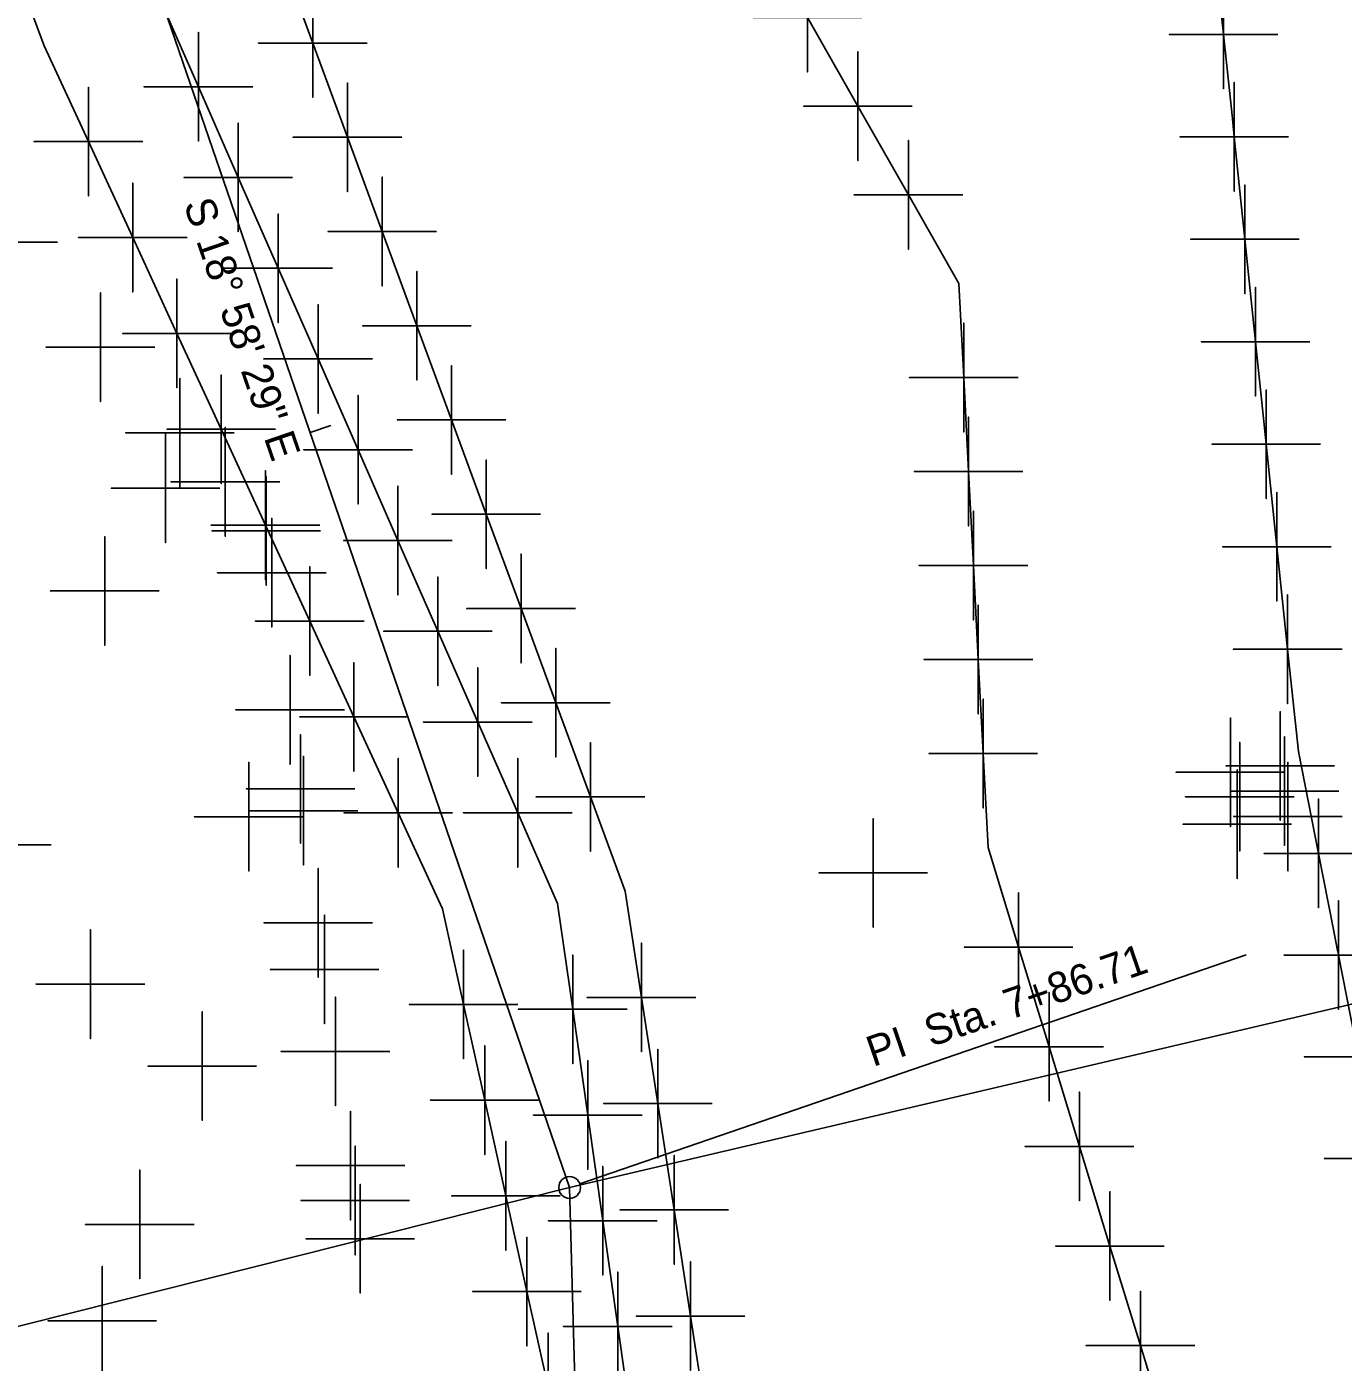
# Model space of a CAD drawing. Extents: x 2260968 to 2264340, y 653057 to 655850.
# Drawn here: x 2261689.1 to 2261749.7, y 654993.6 to 655055 of the extents above; entities that cross this region are included whole.
import ezdxf

# ---------------------------------------------------------------- set-up
doc = ezdxf.new("R2010")
doc.units = 0
for name, color, linetype in [('CL_X_Construction', 7, 'Continuous'), ('Default', 7, 'Continuous'), ('GE_X_CL_10', 7, 'Continuous'), ('GK_Patterns2', 7, 'Continuous')]:
    doc.layers.add(name, color=color, linetype=linetype)

msp = doc.modelspace()

# ---------------------------------------------------------------- linework, layer by layer
at = {"layer": 'CL_X_Construction'}
for p, q in [((2261687.579, 655078.757), (2261714.109, 655001.598)), ((2261687.579, 655078.757), (2261714.109, 655001.598)), ((2261714.109, 655001.598), (2261716.474, 654914.987)), ((2261714.109, 655001.598), (2261716.474, 654914.987))]:
    msp.add_line(p, q, dxfattribs=at)
at = {"layer": 'Default'}
for points in [[(2261720.425, 654990.805), (2261719.672, 654995.689), (2261718.919, 655000.572), (2261718.166, 655005.456), (2261717.413, 655010.339), (2261716.661, 655015.223), (2261715.064, 655019.556), (2261713.468, 655023.89), (2261711.871, 655028.223), (2261710.275, 655032.556), (2261708.678, 655036.889), (2261707.082, 655041.222), (2261705.485, 655045.556), (2261703.889, 655049.889), (2261702.292, 655054.222), (2261700.696, 655058.555), (2261699.362, 655063.307), (2261698.028, 655068.058), (2261696.694, 655072.81), (2261695.36, 655077.561), (2261694.026, 655082.313), (2261692.692, 655087.064), (2261691.423, 655090.297), (2261690.155, 655093.53)], [(2261686.753, 655085.733), (2261687.959, 655081.541), (2261689.164, 655077.349), (2261690.37, 655073.157), (2261691.575, 655068.965), (2261692.781, 655064.773), (2261693.986, 655060.581), (2261695.192, 655056.389), (2261697.028, 655052.215), (2261698.865, 655048.042), (2261700.701, 655043.868), (2261702.538, 655039.695), (2261704.375, 655035.521), (2261706.211, 655031.348), (2261708.048, 655027.174), (2261709.884, 655023.001), (2261711.721, 655018.827), (2261713.557, 655014.654), (2261714.248, 655009.793), (2261714.939, 655004.932), (2261715.63, 655000.071), (2261716.321, 654995.21), (2261717.012, 654990.35)], [(2261713.118, 654992.413), (2261712.146, 654996.814), (2261711.174, 655001.215), (2261710.202, 655005.616), (2261709.231, 655010.017), (2261708.259, 655014.418), (2261706.223, 655018.827), (2261704.188, 655023.236), (2261702.152, 655027.646), (2261700.116, 655032.055), (2261698.081, 655036.464), (2261696.045, 655040.873), (2261694.01, 655045.282), (2261691.974, 655049.691), (2261689.938, 655054.1), (2261688.389, 655058.269)], [(2261725.05, 655055.396), (2261725.05, 655057.896), (2261725.05, 655055.396), (2261722.55, 655055.396), (2261725.05, 655055.396), (2261725.05, 655052.896), (2261725.05, 655055.396), (2261727.55, 655055.396)], [(2261743.887, 655057.515), (2261744.189, 655054.62), (2261744.579, 655050.885), (2261744.595, 655050.73), (2261744.613, 655050.561), (2261744.681, 655049.908), (2261745.173, 655045.197), (2261745.664, 655040.485), (2261746.123, 655036.089), (2261746.156, 655035.774), (2261746.647, 655031.062), (2261747.139, 655026.351), (2261747.63, 655021.639), (2261748.553, 655016.964), (2261749.244, 655013.465), (2261749.435, 655012.496), (2261749.471, 655012.311), (2261749.476, 655012.288), (2261750.399, 655007.613)], [(2261702.292, 655054.222), (2261702.292, 655056.722), (2261702.292, 655054.222), (2261699.792, 655054.222), (2261702.292, 655054.222), (2261702.292, 655051.722), (2261702.292, 655054.222), (2261704.792, 655054.222)], [(2261744.189, 655054.62), (2261744.189, 655057.12), (2261744.189, 655054.62), (2261741.689, 655054.62), (2261744.189, 655054.62), (2261744.189, 655052.12), (2261744.189, 655054.62), (2261746.689, 655054.62)], [(2261741.766, 654989.745), (2261740.364, 654994.327), (2261738.963, 654998.908), (2261737.561, 655003.49), (2261736.16, 655008.071), (2261734.759, 655012.653), (2261733.357, 655017.234), (2261733.133, 655021.556), (2261732.909, 655025.877), (2261732.685, 655030.199), (2261732.461, 655034.521), (2261732.237, 655038.842), (2261732.013, 655043.164), (2261729.692, 655047.241), (2261727.371, 655051.318), (2261725.05, 655055.396)], [(2261697.028, 655052.215), (2261697.028, 655054.715), (2261697.028, 655052.215), (2261694.528, 655052.215), (2261697.028, 655052.215), (2261697.028, 655049.715), (2261697.028, 655052.215), (2261699.528, 655052.215)], [(2261727.371, 655051.318), (2261727.371, 655053.818), (2261727.371, 655051.318), (2261724.871, 655051.318), (2261727.371, 655051.318), (2261727.371, 655048.818), (2261727.371, 655051.318), (2261729.871, 655051.318)], [(2261744.681, 655049.908), (2261744.681, 655052.408), (2261744.681, 655049.908), (2261742.181, 655049.908), (2261744.681, 655049.908), (2261744.681, 655047.408), (2261744.681, 655049.908), (2261747.181, 655049.908)], [(2261691.974, 655049.691), (2261691.974, 655052.191), (2261691.974, 655049.691), (2261689.474, 655049.691), (2261691.974, 655049.691), (2261691.974, 655047.191), (2261691.974, 655049.691), (2261694.474, 655049.691)], [(2261703.889, 655049.889), (2261703.889, 655052.389), (2261703.889, 655049.889), (2261701.389, 655049.889), (2261703.889, 655049.889), (2261703.889, 655047.389), (2261703.889, 655049.889), (2261706.389, 655049.889)], [(2261698.865, 655048.042), (2261698.865, 655050.542), (2261698.865, 655048.042), (2261696.365, 655048.042), (2261698.865, 655048.042), (2261698.865, 655045.542), (2261698.865, 655048.042), (2261701.365, 655048.042)], [(2261729.692, 655047.241), (2261729.692, 655049.741), (2261729.692, 655047.241), (2261727.192, 655047.241), (2261729.692, 655047.241), (2261729.692, 655044.741), (2261729.692, 655047.241), (2261732.192, 655047.241)], [(2261688.044, 655045.071), (2261688.044, 655047.571), (2261688.044, 655045.071), (2261685.544, 655045.071), (2261688.044, 655045.071), (2261688.044, 655042.571), (2261688.044, 655045.071), (2261690.544, 655045.071)], [(2261694.01, 655045.282), (2261694.01, 655047.782), (2261694.01, 655045.282), (2261691.51, 655045.282), (2261694.01, 655045.282), (2261694.01, 655042.782), (2261694.01, 655045.282), (2261696.51, 655045.282)], [(2261705.485, 655045.556), (2261705.485, 655048.056), (2261705.485, 655045.556), (2261702.985, 655045.556), (2261705.485, 655045.556), (2261705.485, 655043.056), (2261705.485, 655045.556), (2261707.985, 655045.556)], [(2261745.173, 655045.197), (2261745.173, 655047.697), (2261745.173, 655045.197), (2261742.673, 655045.197), (2261745.173, 655045.197), (2261745.173, 655042.697), (2261745.173, 655045.197), (2261747.673, 655045.197)], [(2261700.701, 655043.868), (2261700.701, 655046.368), (2261700.701, 655043.868), (2261698.201, 655043.868), (2261700.701, 655043.868), (2261700.701, 655041.368), (2261700.701, 655043.868), (2261703.201, 655043.868)], [(2261696.045, 655040.873), (2261696.045, 655043.373), (2261696.045, 655040.873), (2261693.545, 655040.873), (2261696.045, 655040.873), (2261696.045, 655038.373), (2261696.045, 655040.873), (2261698.545, 655040.873)], [(2261707.082, 655041.222), (2261707.082, 655043.722), (2261707.082, 655041.222), (2261704.582, 655041.222), (2261707.082, 655041.222), (2261707.082, 655038.722), (2261707.082, 655041.222), (2261709.582, 655041.222)], [(2261692.527, 655040.238), (2261692.527, 655042.738), (2261692.527, 655040.238), (2261690.027, 655040.238), (2261692.527, 655040.238), (2261692.527, 655037.738), (2261692.527, 655040.238), (2261695.027, 655040.238)], [(2261745.664, 655040.485), (2261745.664, 655042.985), (2261745.664, 655040.485), (2261743.164, 655040.485), (2261745.664, 655040.485), (2261745.664, 655037.985), (2261745.664, 655040.485), (2261748.164, 655040.485)], [(2261702.538, 655039.695), (2261702.538, 655042.195), (2261702.538, 655039.695), (2261700.038, 655039.695), (2261702.538, 655039.695), (2261702.538, 655037.195), (2261702.538, 655039.695), (2261705.038, 655039.695)], [(2261732.237, 655038.842), (2261732.237, 655041.342), (2261732.237, 655038.842), (2261729.737, 655038.842), (2261732.237, 655038.842), (2261732.237, 655036.342), (2261732.237, 655038.842), (2261734.737, 655038.842)], [(2261698.081, 655036.464), (2261698.081, 655038.964), (2261698.081, 655036.464), (2261695.581, 655036.464), (2261698.081, 655036.464), (2261698.081, 655033.964), (2261698.081, 655036.464), (2261700.581, 655036.464)], [(2261708.678, 655036.889), (2261708.678, 655039.389), (2261708.678, 655036.889), (2261706.178, 655036.889), (2261708.678, 655036.889), (2261708.678, 655034.389), (2261708.678, 655036.889), (2261711.178, 655036.889)], [(2261696.179, 655036.301), (2261696.179, 655038.801), (2261696.179, 655036.301), (2261693.679, 655036.301), (2261696.179, 655036.301), (2261696.179, 655033.801), (2261696.179, 655036.301), (2261698.679, 655036.301)], [(2261746.156, 655035.774), (2261746.156, 655038.274), (2261746.156, 655035.774), (2261743.656, 655035.774), (2261746.156, 655035.774), (2261746.156, 655033.274), (2261746.156, 655035.774), (2261748.656, 655035.774)], [(2261704.375, 655035.521), (2261704.375, 655038.021), (2261704.375, 655035.521), (2261701.875, 655035.521), (2261704.375, 655035.521), (2261704.375, 655033.021), (2261704.375, 655035.521), (2261706.875, 655035.521)], [(2261698.269, 655034.046), (2261698.269, 655036.546), (2261698.269, 655034.046), (2261695.769, 655034.046), (2261698.269, 655034.046), (2261698.269, 655031.546), (2261698.269, 655034.046), (2261700.769, 655034.046)], [(2261732.461, 655034.521), (2261732.461, 655037.021), (2261732.461, 655034.521), (2261729.961, 655034.521), (2261732.461, 655034.521), (2261732.461, 655032.021), (2261732.461, 655034.521), (2261734.961, 655034.521)], [(2261695.52, 655033.75), (2261695.52, 655036.25), (2261695.52, 655033.75), (2261693.02, 655033.75), (2261695.52, 655033.75), (2261695.52, 655031.25), (2261695.52, 655033.75), (2261698.02, 655033.75)], [(2261710.275, 655032.556), (2261710.275, 655035.056), (2261710.275, 655032.556), (2261707.775, 655032.556), (2261710.275, 655032.556), (2261710.275, 655030.056), (2261710.275, 655032.556), (2261712.775, 655032.556)], [(2261700.116, 655032.055), (2261700.116, 655034.555), (2261700.116, 655032.055), (2261697.616, 655032.055), (2261700.116, 655032.055), (2261700.116, 655029.555), (2261700.116, 655032.055), (2261702.616, 655032.055)], [(2261700.151, 655031.791), (2261700.151, 655034.291), (2261700.151, 655031.791), (2261697.651, 655031.791), (2261700.151, 655031.791), (2261700.151, 655029.291), (2261700.151, 655031.791), (2261702.651, 655031.791)], [(2261706.211, 655031.348), (2261706.211, 655033.848), (2261706.211, 655031.348), (2261703.711, 655031.348), (2261706.211, 655031.348), (2261706.211, 655028.848), (2261706.211, 655031.348), (2261708.711, 655031.348)], [(2261746.647, 655031.062), (2261746.647, 655033.562), (2261746.647, 655031.062), (2261744.147, 655031.062), (2261746.647, 655031.062), (2261746.647, 655028.562), (2261746.647, 655031.062), (2261749.147, 655031.062)], [(2261700.407, 655029.868), (2261700.407, 655032.368), (2261700.407, 655029.868), (2261697.907, 655029.868), (2261700.407, 655029.868), (2261700.407, 655027.368), (2261700.407, 655029.868), (2261702.907, 655029.868)], [(2261732.685, 655030.199), (2261732.685, 655032.699), (2261732.685, 655030.199), (2261730.185, 655030.199), (2261732.685, 655030.199), (2261732.685, 655027.699), (2261732.685, 655030.199), (2261735.185, 655030.199)], [(2261692.72, 655029.03), (2261692.72, 655031.53), (2261692.72, 655029.03), (2261690.22, 655029.03), (2261692.72, 655029.03), (2261692.72, 655026.53), (2261692.72, 655029.03), (2261695.22, 655029.03)], [(2261711.871, 655028.223), (2261711.871, 655030.723), (2261711.871, 655028.223), (2261709.371, 655028.223), (2261711.871, 655028.223), (2261711.871, 655025.723), (2261711.871, 655028.223), (2261714.371, 655028.223)], [(2261702.152, 655027.646), (2261702.152, 655030.146), (2261702.152, 655027.646), (2261699.652, 655027.646), (2261702.152, 655027.646), (2261702.152, 655025.146), (2261702.152, 655027.646), (2261704.652, 655027.646)], [(2261708.048, 655027.174), (2261708.048, 655029.674), (2261708.048, 655027.174), (2261705.548, 655027.174), (2261708.048, 655027.174), (2261708.048, 655024.674), (2261708.048, 655027.174), (2261710.548, 655027.174)], [(2261747.139, 655026.351), (2261747.139, 655028.851), (2261747.139, 655026.351), (2261744.639, 655026.351), (2261747.139, 655026.351), (2261747.139, 655023.851), (2261747.139, 655026.351), (2261749.639, 655026.351)], [(2261732.909, 655025.877), (2261732.909, 655028.377), (2261732.909, 655025.877), (2261730.409, 655025.877), (2261732.909, 655025.877), (2261732.909, 655023.377), (2261732.909, 655025.877), (2261735.409, 655025.877)], [(2261701.245, 655023.564), (2261701.245, 655026.064), (2261701.245, 655023.564), (2261698.745, 655023.564), (2261701.245, 655023.564), (2261701.245, 655021.064), (2261701.245, 655023.564), (2261703.745, 655023.564)], [(2261713.468, 655023.89), (2261713.468, 655026.39), (2261713.468, 655023.89), (2261710.968, 655023.89), (2261713.468, 655023.89), (2261713.468, 655021.39), (2261713.468, 655023.89), (2261715.968, 655023.89)], [(2261704.188, 655023.236), (2261704.188, 655025.736), (2261704.188, 655023.236), (2261701.688, 655023.236), (2261704.188, 655023.236), (2261704.188, 655020.736), (2261704.188, 655023.236), (2261706.688, 655023.236)], [(2261709.884, 655023.001), (2261709.884, 655025.501), (2261709.884, 655023.001), (2261707.384, 655023.001), (2261709.884, 655023.001), (2261709.884, 655020.501), (2261709.884, 655023.001), (2261712.384, 655023.001)], [(2261733.133, 655021.556), (2261733.133, 655024.056), (2261733.133, 655021.556), (2261730.633, 655021.556), (2261733.133, 655021.556), (2261733.133, 655019.056), (2261733.133, 655021.556), (2261735.633, 655021.556)], [(2261744.507, 655020.69), (2261744.507, 655023.19), (2261744.507, 655020.69), (2261742.007, 655020.69), (2261744.507, 655020.69), (2261744.507, 655018.19), (2261744.507, 655020.69), (2261747.007, 655020.69)], [(2261746.8, 655020.981), (2261746.8, 655023.481), (2261746.8, 655020.981), (2261744.3, 655020.981), (2261746.8, 655020.981), (2261746.8, 655018.481), (2261746.8, 655020.981), (2261749.3, 655020.981)], [(2261701.729, 655019.925), (2261701.729, 655022.425), (2261701.729, 655019.925), (2261699.229, 655019.925), (2261701.729, 655019.925), (2261701.729, 655017.425), (2261701.729, 655019.925), (2261704.229, 655019.925)], [(2261746.997, 655019.827), (2261746.997, 655022.327), (2261746.997, 655019.827), (2261744.497, 655019.827), (2261746.997, 655019.827), (2261746.997, 655017.327), (2261746.997, 655019.827), (2261749.497, 655019.827)], [(2261715.064, 655019.556), (2261715.064, 655022.056), (2261715.064, 655019.556), (2261712.564, 655019.556), (2261715.064, 655019.556), (2261715.064, 655017.056), (2261715.064, 655019.556), (2261717.564, 655019.556)], [(2261744.935, 655019.565), (2261744.935, 655022.065), (2261744.935, 655019.565), (2261742.435, 655019.565), (2261744.935, 655019.565), (2261744.935, 655017.065), (2261744.935, 655019.565), (2261747.435, 655019.565)], [(2261699.35, 655018.65), (2261699.35, 655021.15), (2261699.35, 655018.65), (2261696.85, 655018.65), (2261699.35, 655018.65), (2261699.35, 655016.15), (2261699.35, 655018.65), (2261701.85, 655018.65)], [(2261701.862, 655018.925), (2261701.862, 655021.425), (2261701.862, 655018.925), (2261699.362, 655018.925), (2261701.862, 655018.925), (2261701.862, 655016.425), (2261701.862, 655018.925), (2261704.362, 655018.925)], [(2261706.223, 655018.827), (2261706.223, 655021.327), (2261706.223, 655018.827), (2261703.723, 655018.827), (2261706.223, 655018.827), (2261706.223, 655016.327), (2261706.223, 655018.827), (2261708.723, 655018.827)], [(2261711.721, 655018.827), (2261711.721, 655021.327), (2261711.721, 655018.827), (2261709.221, 655018.827), (2261711.721, 655018.827), (2261711.721, 655016.327), (2261711.721, 655018.827), (2261714.221, 655018.827)], [(2261747.153, 655018.653), (2261747.153, 655021.153), (2261747.153, 655018.653), (2261744.653, 655018.653), (2261747.153, 655018.653), (2261747.153, 655016.153), (2261747.153, 655018.653), (2261749.653, 655018.653)], [(2261744.82, 655018.305), (2261744.82, 655020.805), (2261744.82, 655018.305), (2261742.32, 655018.305), (2261744.82, 655018.305), (2261744.82, 655015.805), (2261744.82, 655018.305), (2261747.32, 655018.305)], [(2261687.75, 655017.35), (2261687.75, 655019.85), (2261687.75, 655017.35), (2261685.25, 655017.35), (2261687.75, 655017.35), (2261687.75, 655014.85), (2261687.75, 655017.35), (2261690.25, 655017.35)], [(2261748.553, 655016.964), (2261748.553, 655019.464), (2261748.553, 655016.964), (2261746.053, 655016.964), (2261748.553, 655016.964), (2261748.553, 655014.464), (2261748.553, 655016.964), (2261751.053, 655016.964)], [(2261728.076, 655016.063), (2261728.076, 655018.563), (2261728.076, 655016.063), (2261725.576, 655016.063), (2261728.076, 655016.063), (2261728.076, 655013.563), (2261728.076, 655016.063), (2261730.576, 655016.063)], [(2261702.547, 655013.77), (2261702.547, 655016.27), (2261702.547, 655013.77), (2261700.047, 655013.77), (2261702.547, 655013.77), (2261702.547, 655011.27), (2261702.547, 655013.77), (2261705.047, 655013.77)], [(2261734.759, 655012.653), (2261734.759, 655015.153), (2261734.759, 655012.653), (2261732.259, 655012.653), (2261734.759, 655012.653), (2261734.759, 655010.153), (2261734.759, 655012.653), (2261737.259, 655012.653)], [(2261749.476, 655012.288), (2261749.476, 655014.788), (2261749.476, 655012.288), (2261746.976, 655012.288), (2261749.476, 655012.288), (2261749.476, 655009.788), (2261749.476, 655012.288), (2261751.976, 655012.288)], [(2261702.832, 655011.627), (2261702.832, 655014.127), (2261702.832, 655011.627), (2261700.332, 655011.627), (2261702.832, 655011.627), (2261702.832, 655009.127), (2261702.832, 655011.627), (2261705.332, 655011.627)], [(2261692.06, 655010.95), (2261692.06, 655013.45), (2261692.06, 655010.95), (2261689.56, 655010.95), (2261692.06, 655010.95), (2261692.06, 655008.45), (2261692.06, 655010.95), (2261694.56, 655010.95)], [(2261709.231, 655010.017), (2261709.231, 655012.517), (2261709.231, 655010.017), (2261706.731, 655010.017), (2261709.231, 655010.017), (2261709.231, 655007.517), (2261709.231, 655010.017), (2261711.731, 655010.017)], [(2261717.413, 655010.339), (2261717.413, 655012.839), (2261717.413, 655010.339), (2261714.913, 655010.339), (2261717.413, 655010.339), (2261717.413, 655007.839), (2261717.413, 655010.339), (2261719.913, 655010.339)], [(2261714.248, 655009.793), (2261714.248, 655012.293), (2261714.248, 655009.793), (2261711.748, 655009.793), (2261714.248, 655009.793), (2261714.248, 655007.293), (2261714.248, 655009.793), (2261716.748, 655009.793)], [(2261703.334, 655007.857), (2261703.334, 655010.357), (2261703.334, 655007.857), (2261700.834, 655007.857), (2261703.334, 655007.857), (2261703.334, 655005.357), (2261703.334, 655007.857), (2261705.834, 655007.857)], [(2261736.16, 655008.071), (2261736.16, 655010.571), (2261736.16, 655008.071), (2261733.66, 655008.071), (2261736.16, 655008.071), (2261736.16, 655005.571), (2261736.16, 655008.071), (2261738.66, 655008.071)], [(2261750.399, 655007.613), (2261750.399, 655010.113), (2261750.399, 655007.613), (2261747.899, 655007.613), (2261750.399, 655007.613), (2261750.399, 655005.113), (2261750.399, 655007.613), (2261752.899, 655007.613)], [(2261697.21, 655007.18), (2261697.21, 655009.68), (2261697.21, 655007.18), (2261694.71, 655007.18), (2261697.21, 655007.18), (2261697.21, 655004.68), (2261697.21, 655007.18), (2261699.71, 655007.18)], [(2261710.202, 655005.616), (2261710.202, 655008.116), (2261710.202, 655005.616), (2261707.702, 655005.616), (2261710.202, 655005.616), (2261710.202, 655003.116), (2261710.202, 655005.616), (2261712.702, 655005.616)], [(2261718.166, 655005.456), (2261718.166, 655007.956), (2261718.166, 655005.456), (2261715.666, 655005.456), (2261718.166, 655005.456), (2261718.166, 655002.956), (2261718.166, 655005.456), (2261720.666, 655005.456)], [(2261714.939, 655004.932), (2261714.939, 655007.432), (2261714.939, 655004.932), (2261712.439, 655004.932), (2261714.939, 655004.932), (2261714.939, 655002.432), (2261714.939, 655004.932), (2261717.439, 655004.932)], [(2261737.561, 655003.49), (2261737.561, 655005.99), (2261737.561, 655003.49), (2261735.061, 655003.49), (2261737.561, 655003.49), (2261737.561, 655000.99), (2261737.561, 655003.49), (2261740.061, 655003.49)], [(2261751.321, 655002.937), (2261751.321, 655005.437), (2261751.321, 655002.937), (2261748.821, 655002.937), (2261751.321, 655002.937), (2261751.321, 655000.437), (2261751.321, 655002.937), (2261753.821, 655002.937)], [(2261704.032, 655002.604), (2261704.032, 655005.104), (2261704.032, 655002.604), (2261701.532, 655002.604), (2261704.032, 655002.604), (2261704.032, 655000.104), (2261704.032, 655002.604), (2261706.532, 655002.604)], [(2261704.245, 655001.003), (2261704.245, 655003.503), (2261704.245, 655001.003), (2261701.745, 655001.003), (2261704.245, 655001.003), (2261704.245, 654998.503), (2261704.245, 655001.003), (2261706.745, 655001.003)], [(2261711.174, 655001.215), (2261711.174, 655003.715), (2261711.174, 655001.215), (2261708.674, 655001.215), (2261711.174, 655001.215), (2261711.174, 654998.715), (2261711.174, 655001.215), (2261713.674, 655001.215)], [(2261718.919, 655000.572), (2261718.919, 655003.072), (2261718.919, 655000.572), (2261716.419, 655000.572), (2261718.919, 655000.572), (2261718.919, 654998.072), (2261718.919, 655000.572), (2261721.419, 655000.572)], [(2261694.33, 654999.9), (2261694.33, 655002.4), (2261694.33, 654999.9), (2261691.83, 654999.9), (2261694.33, 654999.9), (2261694.33, 654997.4), (2261694.33, 654999.9), (2261696.83, 654999.9)], [(2261715.63, 655000.071), (2261715.63, 655002.571), (2261715.63, 655000.071), (2261713.13, 655000.071), (2261715.63, 655000.071), (2261715.63, 654997.571), (2261715.63, 655000.071), (2261718.13, 655000.071)], [(2261704.479, 654999.241), (2261704.479, 655001.741), (2261704.479, 654999.241), (2261701.979, 654999.241), (2261704.479, 654999.241), (2261704.479, 654996.741), (2261704.479, 654999.241), (2261706.979, 654999.241)], [(2261738.963, 654998.908), (2261738.963, 655001.408), (2261738.963, 654998.908), (2261736.463, 654998.908), (2261738.963, 654998.908), (2261738.963, 654996.408), (2261738.963, 654998.908), (2261741.463, 654998.908)], [(2261712.146, 654996.814), (2261712.146, 654999.314), (2261712.146, 654996.814), (2261709.646, 654996.814), (2261712.146, 654996.814), (2261712.146, 654994.314), (2261712.146, 654996.814), (2261714.646, 654996.814)], [(2261692.61, 654995.47), (2261692.61, 654997.97), (2261692.61, 654995.47), (2261690.11, 654995.47), (2261692.61, 654995.47), (2261692.61, 654992.97), (2261692.61, 654995.47), (2261695.11, 654995.47)], [(2261719.672, 654995.689), (2261719.672, 654998.189), (2261719.672, 654995.689), (2261717.172, 654995.689), (2261719.672, 654995.689), (2261719.672, 654993.189), (2261719.672, 654995.689), (2261722.172, 654995.689)], [(2261716.321, 654995.21), (2261716.321, 654997.71), (2261716.321, 654995.21), (2261713.821, 654995.21), (2261716.321, 654995.21), (2261716.321, 654992.71), (2261716.321, 654995.21), (2261718.821, 654995.21)], [(2261740.364, 654994.327), (2261740.364, 654996.827), (2261740.364, 654994.327), (2261737.864, 654994.327), (2261740.364, 654994.327), (2261740.364, 654991.827), (2261740.364, 654994.327), (2261742.864, 654994.327)], [(2261713.118, 654992.413), (2261713.118, 654994.913), (2261713.118, 654992.413), (2261710.618, 654992.413), (2261713.118, 654992.413), (2261713.118, 654989.913), (2261713.118, 654992.413), (2261715.618, 654992.413)]]:
    msp.add_lwpolyline(points, dxfattribs=at)
at = {"layer": 'GE_X_CL_10'}
for p, q in [((2261687.579, 655078.757), (2261714.109, 655001.598)), ((2261702.172, 655036.315), (2261703.118, 655036.64)), ((2261702.172, 655036.315), (2261703.118, 655036.64)), ((2261714.582, 655001.761), (2261745.234, 655012.3)), ((2261714.582, 655001.761), (2261745.234, 655012.3)), ((2261714.109, 655001.598), (2261716.474, 654914.987))]:
    msp.add_line(p, q, dxfattribs=at)
msp.add_circle((2261714.109, 655001.598), 0.5, dxfattribs=at)
msp.add_circle((2261714.109, 655001.598), 0.5, dxfattribs=at)
at = {"layer": 'GK_Patterns2'}
msp.add_lwpolyline([(2261632.795, 654981.138), (2261714.109, 655001.598), (2261950.979, 655057.107)], dxfattribs=at)

# ---------------------------------------------------------------- texts
at = {"layer": 'GE_X_CL_10'}
for s, rotation, p in [('S 18%%d 58\' 29" E', 288.97458, (2261696.34, 655046.817)), ('PI  Sta. 7+86.71', 18.97458, (2261728.066, 655007.138)), ('PI  Sta. 7+86.71', 18.97458, (2261728.066, 655007.138))]:
    msp.add_text(s, height=1.4, rotation=rotation, dxfattribs=at).set_placement(p)

doc.saveas('drawing.dxf')
